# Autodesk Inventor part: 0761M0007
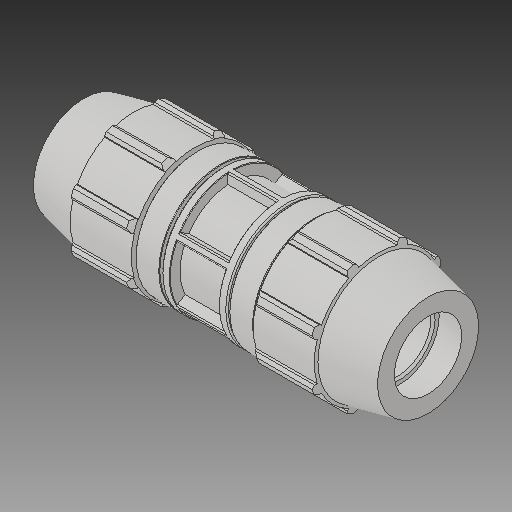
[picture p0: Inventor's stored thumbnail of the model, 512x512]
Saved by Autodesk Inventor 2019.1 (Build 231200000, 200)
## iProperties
Created: 2017-02
Part Number: 0761M0007
Material: Generic
Description: PLASSON REPAIR COUPLER 3/4'' - 3/4''
Document SubType Name: Modeling
Designer: KIM
Mass: 2544.89 g
Surface Area: 2949.22 cm^2
Volume: 2544.89 cm^3
Density: 1 g/cm^3
Appearance: Default
Author: KIM
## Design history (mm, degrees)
derived "0761M.ipt"
feature "Solid1::0761M.ipt"
tag "TaggingFeature1"
body "Solid1"
other parameters: "d1" = 135.89, "d2" = 26.6, "d4" = 11.32417, "d5" = 19.41286, "d7" = 54.102, "d8" = 40.5765, "d9" = 19.41286, "d11" = 9.35567, "d12" = 43.2816, "d13" = 120 deg, "d14" = 39.9, "d15" = 12 deg, "d16" = 48.6918, "d19" = 35 deg, "d20" = 17.5 deg, "d21" = 50.31486, "d23" = 0, "d25" = 360 deg, "d27" = 1.08204, "d33" = 0.2, "d34" = 2.7051, "d36" = 0, "d37" = 0.532, "d38" = 0.532, "d40" = 360 deg, "d42" = 24.4602, "d43" = 1.62306, "d46" = 0.798, "d50" = 0.88719, "d51" = 43.2816, "d52" = 0.88719, "d_" = 26.6, "E_" = 54.102, "H_" = 135.89, "l_" = 59.944, "d49" = 11.13004
